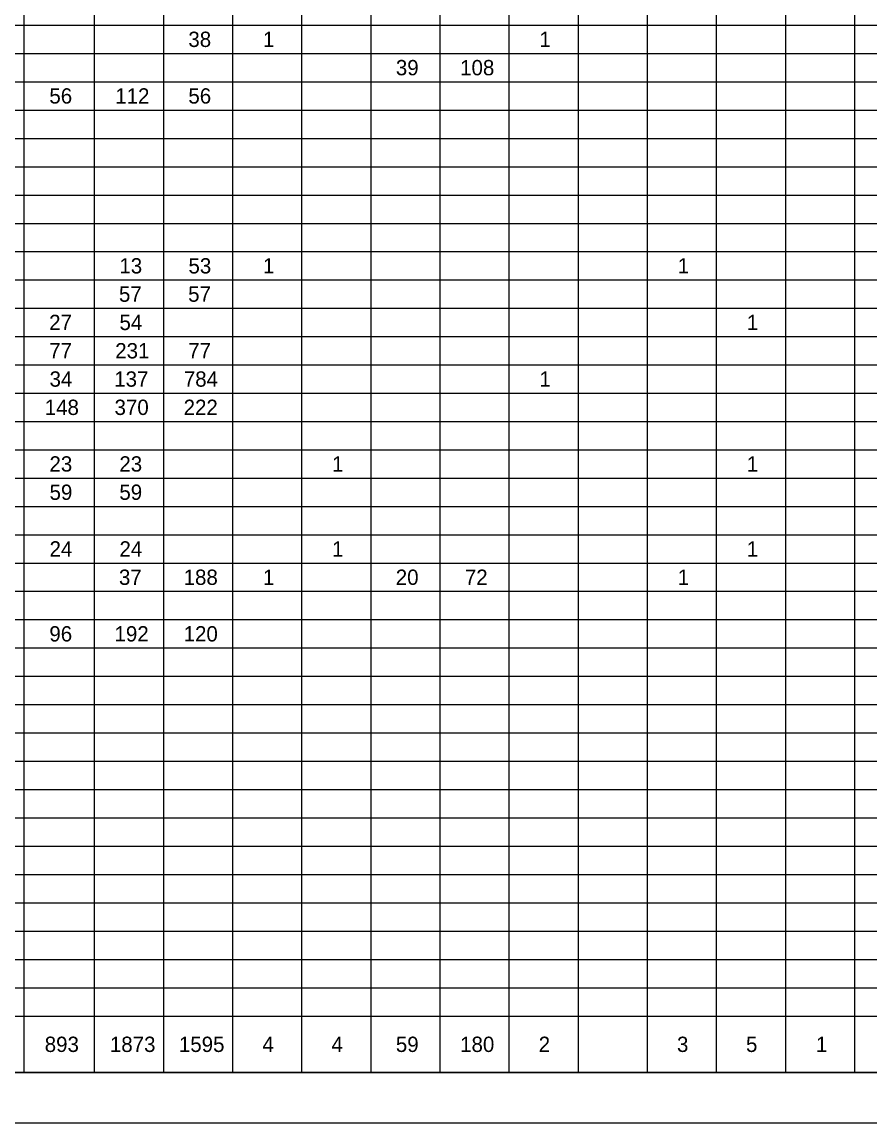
# Model space of a CAD drawing. Extents: x -0.2 to 34, y 0 to 22.
# Drawn here: x 16.87 to 25.29, y 0 to 10.93 of the extents above; entities that cross this region are included whole.
import ezdxf

# ---------------------------------------------------------------- set-up
doc = ezdxf.new("R2010")
doc.units = 0
for name, color, linetype in [('DV_X_Property_Line', 7, 'Continuous'), ('RW_X_CL', 7, 'Continuous'), ('SV_X_Mon_Cells_Found', 7, 'Continuous')]:
    doc.layers.add(name, color=color, linetype=linetype)

msp = doc.modelspace()

# ---------------------------------------------------------------- linework, layer by layer
at = {"layer": 'DV_X_Property_Line'}
msp.add_lwpolyline([(1.5, 21.5), (33.5, 21.5), (33.5, 0.5), (1.5, 0.5)], close=True, dxfattribs=at)
at = {"layer": 'RW_X_CL'}
msp.add_lwpolyline([(0, 0), (34, 0), (34, 22), (0, 22)], close=True, dxfattribs=at)
at = {"layer": 'SV_X_Mon_Cells_Found'}
for p, q in [((16.889, 21.5), (16.889, 0.5)), ((17.59, 21.5), (17.59, 0.5)), ((18.276, 21.5), (18.276, 0.5)), ((18.962, 21.5), (18.962, 0.5)), ((19.648, 21.5), (19.648, 0.5)), ((20.334, 21.5), (20.334, 0.5)), ((21.021, 21.5), (21.021, 0.5)), ((21.707, 21.5), (21.707, 0.5)), ((22.393, 21.5), (22.393, 0.5)), ((23.079, 21.5), (23.079, 0.5)), ((23.765, 21.5), (23.765, 0.5)), ((24.452, 21.5), (24.452, 0.5)), ((25.138, 21.5), (25.138, 0.5)), ((1.5, 10.901), (32, 10.901)), ((1.5, 10.62), (32, 10.62)), ((1.5, 10.339), (32, 10.339)), ((1.5, 10.057), (32, 10.057)), ((1.5, 9.776), (32, 9.776)), ((1.5, 9.495), (32, 9.495)), ((1.5, 9.214), (32, 9.214)), ((1.5, 8.933), (32, 8.933)), ((1.5, 8.652), (32, 8.652)), ((1.5, 8.371), (32, 8.371)), ((1.5, 8.09), (32, 8.09)), ((1.5, 7.809), (32, 7.809)), ((1.5, 7.528), (32, 7.528)), ((1.5, 7.246), (32, 7.246)), ((1.5, 6.965), (32, 6.965)), ((1.5, 6.684), (32, 6.684)), ((1.5, 6.403), (32, 6.403)), ((1.5, 6.122), (32, 6.122)), ((1.5, 5.841), (32, 5.841)), ((1.5, 5.56), (32, 5.56)), ((1.5, 5.279), (32, 5.279)), ((1.5, 4.998), (32, 4.998)), ((1.5, 4.717), (32, 4.717)), ((1.5, 4.435), (32, 4.435)), ((1.5, 4.154), (32, 4.154)), ((1.5, 3.873), (32, 3.873)), ((1.5, 3.592), (32, 3.592)), ((1.5, 3.311), (32, 3.311)), ((1.5, 3.03), (32, 3.03)), ((1.5, 2.749), (32, 2.749)), ((1.5, 2.468), (32, 2.468)), ((1.5, 2.187), (32, 2.187)), ((1.5, 1.906), (32, 1.906)), ((1.5, 1.624), (32, 1.624)), ((1.5, 1.343), (32, 1.343)), ((1.5, 1.062), (32, 1.062)), ((1.5, 0.5), (32, 0.5))]:
    msp.add_line(p, q, dxfattribs=at)

# ---------------------------------------------------------------- texts
for s, height, p in [('38', 0.1521, (18.524, 10.684)), ('1', 0.152, (19.265, 10.684)), ('1', 0.152, (22.009, 10.684)), ('39', 0.1521, (20.584, 10.403)), ('108', 0.1521, (21.222, 10.403)), ('56', 0.1521, (17.144, 10.122)), ('112', 0.1521, (17.798, 10.122)), ('56', 0.1521, (18.524, 10.122)), ('13', 0.1521, (17.839, 8.435)), ('53', 0.1521, (18.525, 8.435)), ('1', 0.152, (19.265, 8.435)), ('1', 0.152, (23.382, 8.435)), ('57', 0.1521, (17.835, 8.154)), ('57', 0.1521, (18.522, 8.154)), ('27', 0.1521, (17.142, 7.873)), ('54', 0.1521, (17.84, 7.873)), ('1', 0.152, (24.068, 7.873)), ('77', 0.1521, (17.142, 7.592)), ('231', 0.1521, (17.798, 7.592)), ('77', 0.1521, (18.522, 7.592)), ('34', 0.1521, (17.146, 7.311)), ('137', 0.1521, (17.788, 7.311)), ('784', 0.1521, (18.479, 7.311)), ('1', 0.152, (22.009, 7.311)), ('148', 0.1521, (17.098, 7.03)), ('370', 0.1521, (17.791, 7.03)), ('222', 0.1521, (18.477, 7.03)), ('23', 0.1521, (17.145, 6.468)), ('23', 0.1521, (17.839, 6.468)), ('1', 0.152, (19.951, 6.468)), ('1', 0.152, (24.068, 6.468)), ('59', 0.1521, (17.146, 6.187)), ('59', 0.1521, (17.839, 6.187)), ('24', 0.1521, (17.146, 5.624)), ('24', 0.1521, (17.84, 5.624)), ('1', 0.152, (19.951, 5.624)), ('1', 0.152, (24.068, 5.624)), ('37', 0.1521, (17.835, 5.343)), ('188', 0.1521, (18.477, 5.343)), ('1', 0.152, (19.265, 5.343)), ('20', 0.1521, (20.583, 5.343)), ('72', 0.1521, (21.269, 5.343)), ('1', 0.152, (23.382, 5.343)), ('96', 0.1521, (17.144, 4.781)), ('192', 0.1521, (17.791, 4.781)), ('120', 0.1521, (18.477, 4.781)), ('893', 0.1521, (17.098, 0.705)), ('1873', 0.1521, (17.745, 0.705)), ('1595', 0.1521, (18.43, 0.705)), ('4', 0.152, (19.259, 0.705)), ('4', 0.152, (19.945, 0.705)), ('59', 0.1521, (20.584, 0.705)), ('180', 0.1521, (21.222, 0.705)), ('2', 0.152, (22.002, 0.705)), ('3', 0.152, (23.375, 0.705)), ('5', 0.152, (24.06, 0.705)), ('1', 0.152, (24.754, 0.705))]:
    msp.add_text(s, height=height, dxfattribs=at).set_placement(p)

doc.saveas('drawing.dxf')
